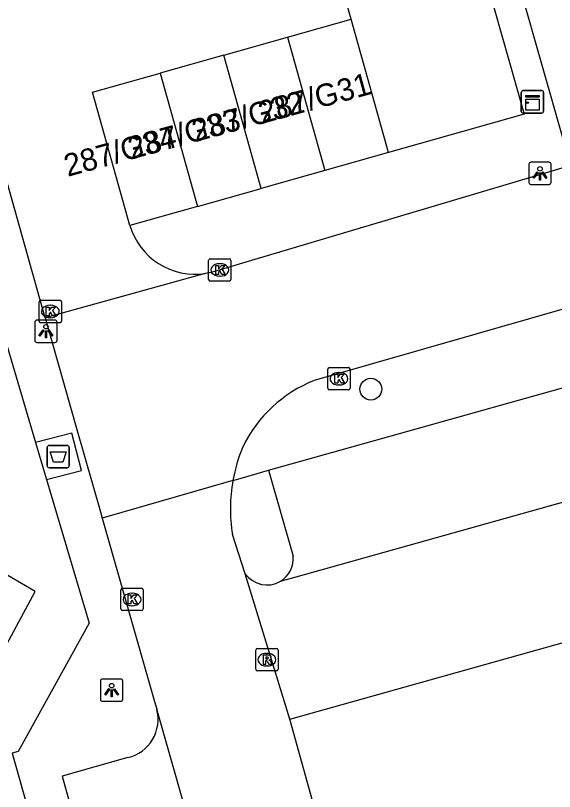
# Model space of a CAD drawing. Extents: x 159689 to 160786, y 387323 to 388339.
# Drawn here: x 159796.06 to 159820.18, y 387937.49 to 387972.19 of the extents above; entities that cross this region are included whole.
import ezdxf

# ---------------------------------------------------------------- set-up
doc = ezdxf.new("R2010")
doc.units = 0
for name, color, linetype in [('IMGEO_Afval_apart_plaats', 7, 'Continuous'), ('IMGEO_Boom', 7, 'Continuous'), ('IMGEO_Kast', 7, 'Continuous'), ('IMGEO_Kolk', 7, 'Continuous'), ('IMGEO_Lichtpunt', 7, 'Continuous'), ('IMGEO_Pand', 7, 'Continuous'), ('IMGEO_Pand_nummerreeks', 7, 'Continuous'), ('IMGEO_Rijbaan_lokaal_open', 7, 'Continuous'), ('IMGEO_Rioolput', 7, 'Continuous'), ('IMGEO_Voetpad_gesloten', 7, 'Continuous'), ('IMGEO_Voetpad_open', 7, 'Continuous')]:
    doc.layers.add(name, color=color, linetype=linetype)

msp = doc.modelspace()

# ---------------------------------------------------------------- linework, layer by layer
at = {"layer": 'IMGEO_Afval_apart_plaats'}
for p, q in [((159797.479, 387952.066), (159797.479, 387952.866)), ((159797.479, 387952.866), (159797.479, 387952.066)), ((159797.579, 387952.966), (159798.369, 387952.966)), ((159798.369, 387952.966), (159797.579, 387952.966)), ((159798.469, 387952.866), (159798.469, 387952.066)), ((159798.469, 387952.066), (159798.469, 387952.866)), ((159798.369, 387951.966), (159797.579, 387951.966)), ((159797.579, 387951.966), (159798.369, 387951.966))]:
    msp.add_line(p, q, dxfattribs=at)
msp.add_lwpolyline([(159797.622, 387952.68), (159798.326, 387952.68), (159798.177, 387952.21), (159797.771, 387952.21), (159797.622, 387952.68)], dxfattribs=at)
for centre, start, end in [((159797.579, 387952.866), 90, 180), ((159797.579, 387952.866), 90, 180), ((159798.369, 387952.866), 0, 90), ((159798.369, 387952.866), 360, 90), ((159797.579, 387952.066), 180, 270), ((159797.579, 387952.066), 180, 270), ((159798.369, 387952.066), 270, 0), ((159798.369, 387952.066), 270, 0)]:
    msp.add_arc(centre, 0.1, start, end, dxfattribs=at)
at = {"layer": 'IMGEO_Boom'}
msp.add_circle((159811.962, 387955.482), 0.489, dxfattribs=at)
at = {"layer": 'IMGEO_Kast'}
for p, q in [((159818.695, 387967.903), (159818.695, 387968.744)), ((159818.695, 387968.744), (159818.695, 387967.903)), ((159818.77, 387968.828), (159819.611, 387968.828)), ((159819.611, 387968.828), (159818.77, 387968.828)), ((159819.695, 387968.753), (159819.695, 387967.912)), ((159819.695, 387967.912), (159819.695, 387968.753)), ((159819.62, 387967.828), (159818.779, 387967.828)), ((159818.779, 387967.828), (159819.62, 387967.828))]:
    msp.add_line(p, q, dxfattribs=at)
for points in [[(159818.89, 387968.618), (159819.49, 387968.618), (159819.49, 387968.533), (159818.89, 387968.533), (159818.89, 387968.618)], [(159818.89, 387968.443), (159819.49, 387968.443), (159819.49, 387967.954), (159818.89, 387967.954), (159818.89, 387968.443)]]:
    msp.add_lwpolyline(points, dxfattribs=at)
msp.add_circle((159818.974, 387968.292), 0.0377, dxfattribs=at)
for centre, start, end in [((159818.773, 387968.75), 92.4484, 184.2845), ((159818.773, 387968.75), 92.4484, 184.2845), ((159819.617, 387968.75), 2.4484, 94.2845), ((159819.617, 387968.75), 2.4484, 94.2845), ((159818.773, 387967.906), 182.4484, 274.2845), ((159818.773, 387967.906), 182.4484, 274.2845), ((159819.617, 387967.906), 272.4484, 4.2845), ((159819.617, 387967.906), 272.4484, 4.2845)]:
    msp.add_arc(centre, 0.0779, start, end, dxfattribs=at)
at = {"layer": 'IMGEO_Kolk'}
for p, q in [((159804.704, 387960.386), (159804.704, 387961.238)), ((159804.779, 387961.312), (159805.631, 387961.312)), ((159805.705, 387961.238), (159805.705, 387960.386)), ((159805.192, 387961.092), (159805.217, 387961.092)), ((159805.215, 387960.532), (159805.19, 387960.532)), ((159805.631, 387960.312), (159804.779, 387960.312)), ((159797.122, 387958.527), (159797.122, 387959.379)), ((159797.197, 387959.453), (159798.049, 387959.453)), ((159798.123, 387959.379), (159798.123, 387958.527)), ((159797.61, 387959.233), (159797.635, 387959.233)), ((159797.633, 387958.673), (159797.608, 387958.673)), ((159798.049, 387958.453), (159797.197, 387958.453)), ((159810.036, 387955.521), (159810.036, 387956.373)), ((159810.111, 387956.447), (159810.963, 387956.447)), ((159811.037, 387956.373), (159811.037, 387955.521)), ((159810.524, 387956.227), (159810.549, 387956.227)), ((159810.547, 387955.667), (159810.522, 387955.667)), ((159810.963, 387955.447), (159810.111, 387955.447)), ((159800.856, 387946.577), (159801.708, 387946.577)), ((159800.781, 387945.651), (159800.781, 387946.503)), ((159801.269, 387946.357), (159801.294, 387946.357)), ((159801.782, 387946.503), (159801.782, 387945.651)), ((159801.708, 387945.577), (159800.856, 387945.577)), ((159801.292, 387945.797), (159801.267, 387945.797))]:
    msp.add_line(p, q, dxfattribs=at)
for points in [[(159804.704, 387960.386), (159804.704, 387961.238)], [(159804.779, 387961.312), (159805.631, 387961.312)], [(159805.705, 387961.238), (159805.705, 387960.386)], [(159805.025, 387961.012), (159805.148, 387961.012), (159805.148, 387960.861), (159805.278, 387961.012), (159805.442, 387961.012), (159805.296, 387960.861), (159805.449, 387960.612), (159805.297, 387960.612), (159805.212, 387960.776), (159805.148, 387960.709), (159805.148, 387960.612), (159805.025, 387960.612), (159805.025, 387961.012)], [(159805.631, 387960.312), (159804.779, 387960.312)], [(159797.122, 387958.527), (159797.122, 387959.379)], [(159797.197, 387959.453), (159798.049, 387959.453)], [(159798.123, 387959.379), (159798.123, 387958.527)], [(159797.443, 387959.153), (159797.566, 387959.153), (159797.566, 387959.002), (159797.696, 387959.153), (159797.86, 387959.153), (159797.714, 387959.002), (159797.867, 387958.753), (159797.715, 387958.753), (159797.63, 387958.917), (159797.566, 387958.85), (159797.566, 387958.753), (159797.443, 387958.753), (159797.443, 387959.153)], [(159798.049, 387958.453), (159797.197, 387958.453)], [(159810.036, 387955.521), (159810.036, 387956.373)], [(159810.111, 387956.447), (159810.963, 387956.447)], [(159811.037, 387956.373), (159811.037, 387955.521)], [(159810.357, 387956.147), (159810.48, 387956.147), (159810.48, 387955.996), (159810.61, 387956.147), (159810.774, 387956.147), (159810.628, 387955.996), (159810.781, 387955.747), (159810.629, 387955.747), (159810.544, 387955.911), (159810.48, 387955.844), (159810.48, 387955.747), (159810.357, 387955.747), (159810.357, 387956.147)], [(159810.963, 387955.447), (159810.111, 387955.447)], [(159800.856, 387946.577), (159801.708, 387946.577)], [(159800.781, 387945.651), (159800.781, 387946.503)], [(159801.102, 387946.277), (159801.225, 387946.277), (159801.225, 387946.126), (159801.355, 387946.277), (159801.519, 387946.277), (159801.373, 387946.126), (159801.526, 387945.877), (159801.374, 387945.877), (159801.289, 387946.041), (159801.225, 387945.974), (159801.225, 387945.877), (159801.102, 387945.877), (159801.102, 387946.277)], [(159801.782, 387946.503), (159801.782, 387945.651)], [(159801.708, 387945.577), (159800.856, 387945.577)]]:
    msp.add_lwpolyline(points, dxfattribs=at)
for centre, start, end in [((159804.781, 387961.236), 91.552, 178.448), ((159804.781, 387961.236), 91.552, 178.448), ((159805.629, 387961.236), 1.552, 88.448), ((159805.629, 387961.236), 1.552, 88.448), ((159804.781, 387960.388), 181.552, 268.448), ((159804.781, 387960.388), 181.552, 268.448), ((159805.629, 387960.388), 271.552, 358.448), ((159805.629, 387960.388), 271.552, 358.448), ((159797.199, 387959.377), 91.552, 178.448), ((159797.199, 387959.377), 91.552, 178.448), ((159798.047, 387959.377), 1.552, 88.448), ((159798.047, 387959.377), 1.552, 88.448), ((159797.199, 387958.529), 181.552, 268.448), ((159797.199, 387958.529), 181.552, 268.448), ((159798.047, 387958.529), 271.552, 358.448), ((159798.047, 387958.529), 271.552, 358.448), ((159810.113, 387956.371), 91.552, 178.448), ((159810.113, 387956.371), 91.552, 178.448), ((159810.961, 387956.371), 1.552, 88.448), ((159810.961, 387956.371), 1.552, 88.448), ((159810.113, 387955.523), 181.552, 268.448), ((159810.113, 387955.523), 181.552, 268.448), ((159810.961, 387955.523), 271.552, 358.448), ((159810.961, 387955.523), 271.552, 358.448), ((159800.858, 387946.501), 91.552, 178.448), ((159800.858, 387946.501), 91.552, 178.448), ((159801.706, 387946.501), 1.552, 88.448), ((159801.706, 387946.501), 1.552, 88.448), ((159800.858, 387945.653), 181.552, 268.448), ((159800.858, 387945.653), 181.552, 268.448), ((159801.706, 387945.653), 271.552, 358.448), ((159801.706, 387945.653), 271.552, 358.448)]:
    msp.add_arc(centre, 0.0765, start, end, dxfattribs=at)
for centre, major_axis, ratio, start_param, end_param in [((159805.191, 387960.812), (-0.387, 0.002), 0.722429, 4.712389, 7.853982), ((159805.216, 387960.812), (-0.39, 0.002), 0.717154, 1.570796, 4.712389), ((159797.609, 387958.953), (-0.387, 0.002), 0.722429, 4.712389, 7.853982), ((159797.634, 387958.953), (-0.39, 0.002), 0.717154, 1.570796, 4.712389), ((159810.523, 387955.947), (-0.387, 0.002), 0.722429, 4.712389, 7.853982), ((159810.548, 387955.947), (-0.39, 0.002), 0.717154, 1.570796, 4.712389), ((159801.268, 387946.077), (-0.387, 0.002), 0.722429, 4.712389, 7.853982), ((159801.293, 387946.077), (-0.39, 0.002), 0.717154, 1.570796, 4.712389)]:
    msp.add_ellipse(centre, major_axis=major_axis, ratio=ratio, start_param=start_param, end_param=end_param, dxfattribs=at)
at = {"layer": 'IMGEO_Lichtpunt'}
for p, q in [((159819.935, 387965.629), (159819.127, 387965.629)), ((159819.935, 387965.629), (159819.127, 387965.629)), ((159819.033, 387965.534), (159819.033, 387964.727)), ((159819.033, 387965.534), (159819.033, 387964.727)), ((159820.029, 387964.727), (159820.029, 387965.534)), ((159820.029, 387964.727), (159820.029, 387965.534)), ((159819.127, 387964.633), (159819.935, 387964.633)), ((159819.127, 387964.633), (159819.935, 387964.633)), ((159796.926, 387958.474), (159796.926, 387957.667)), ((159796.926, 387958.474), (159796.926, 387957.667)), ((159797.828, 387958.569), (159797.02, 387958.569)), ((159797.828, 387958.569), (159797.02, 387958.569)), ((159797.922, 387957.667), (159797.922, 387958.474)), ((159797.922, 387957.667), (159797.922, 387958.474)), ((159797.02, 387957.573), (159797.828, 387957.573)), ((159797.02, 387957.573), (159797.828, 387957.573)), ((159799.867, 387942.424), (159799.867, 387941.617)), ((159799.867, 387942.424), (159799.867, 387941.617)), ((159800.769, 387942.519), (159799.961, 387942.519)), ((159800.769, 387942.519), (159799.961, 387942.519)), ((159800.863, 387941.617), (159800.863, 387942.424)), ((159800.863, 387941.617), (159800.863, 387942.424)), ((159799.961, 387941.523), (159800.769, 387941.523)), ((159799.961, 387941.523), (159800.769, 387941.523))]:
    msp.add_line(p, q, dxfattribs=at)
for points in [[(159819.407, 387965.198), (159819.446, 387965.17), (159819.258, 387964.908), (159819.22, 387964.935), (159819.407, 387965.198)], [(159819.509, 387965.15), (159819.556, 387965.15), (159819.556, 387964.828), (159819.509, 387964.828), (159819.509, 387965.15)], [(159819.619, 387965.17), (159819.657, 387965.197), (159819.844, 387964.935), (159819.805, 387964.907), (159819.619, 387965.17)], [(159797.3, 387958.138), (159797.339, 387958.11), (159797.151, 387957.848), (159797.113, 387957.875), (159797.3, 387958.138)], [(159797.402, 387958.09), (159797.449, 387958.09), (159797.449, 387957.768), (159797.402, 387957.768), (159797.402, 387958.09)], [(159797.512, 387958.11), (159797.55, 387958.137), (159797.737, 387957.875), (159797.698, 387957.847), (159797.512, 387958.11)], [(159800.241, 387942.088), (159800.28, 387942.06), (159800.092, 387941.798), (159800.054, 387941.825), (159800.241, 387942.088)], [(159800.343, 387942.04), (159800.39, 387942.04), (159800.39, 387941.718), (159800.343, 387941.718), (159800.343, 387942.04)], [(159800.453, 387942.06), (159800.491, 387942.087), (159800.678, 387941.825), (159800.639, 387941.797), (159800.453, 387942.06)]]:
    msp.add_lwpolyline(points, dxfattribs=at)
for centre in [(159819.532, 387965.332), (159797.425, 387958.272), (159800.366, 387942.222)]:
    msp.add_circle(centre, 0.0994, dxfattribs=at)
for centre, start, end in [((159819.127, 387965.534), 90, 180), ((159819.127, 387965.534), 90, 180), ((159819.935, 387965.534), 0, 90), ((159819.935, 387965.534), 0, 90), ((159819.127, 387964.727), 180, 270), ((159819.127, 387964.727), 180, 270), ((159819.935, 387964.727), 270, 0), ((159819.935, 387964.727), 270, 360), ((159797.02, 387958.474), 90, 180), ((159797.02, 387958.474), 90, 180), ((159797.828, 387958.474), 0, 90), ((159797.828, 387958.474), 0, 90), ((159797.02, 387957.667), 180, 270), ((159797.02, 387957.667), 180, 270), ((159797.828, 387957.667), 270, 0), ((159797.828, 387957.667), 270, 360), ((159799.961, 387942.424), 90, 180), ((159799.961, 387942.424), 90, 180), ((159800.769, 387942.424), 0, 90), ((159800.769, 387942.424), 0, 90), ((159799.961, 387941.617), 180, 270), ((159799.961, 387941.617), 180, 270), ((159800.769, 387941.617), 270, 0), ((159800.769, 387941.617), 270, 360)]:
    msp.add_arc(centre, 0.0946, start, end, dxfattribs=at)
at = {"layer": 'IMGEO_Pand'}
for points in [[(159816.341, 387976.561), (159817.139, 387973.727), (159818.817, 387967.77), (159812.759, 387966.064)], [(159811.081, 387972.02), (159810.283, 387974.854)], [(159808.231, 387971.217), (159811.081, 387972.02)], [(159812.759, 387966.064), (159811.081, 387972.02)], [(159805.381, 387970.414), (159808.231, 387971.217)], [(159808.231, 387971.217), (159809.909, 387965.261)], [(159805.381, 387970.414), (159802.531, 387969.611)], [(159807.059, 387964.458), (159805.381, 387970.414)], [(159801.187, 387962.804), (159799.509, 387968.76), (159802.531, 387969.611)], [(159802.531, 387969.611), (159804.209, 387963.655)], [(159812.759, 387966.064), (159809.909, 387965.261)], [(159809.909, 387965.261), (159807.059, 387964.458)], [(159804.209, 387963.655), (159807.059, 387964.458)], [(159804.209, 387963.655), (159801.187, 387962.804)], [(159817.654, 387873.188), (159814.236, 387875.206), (159812.839, 387874.816), (159811.729, 387878.794), (159794.957, 387938.93), (159793.845, 387942.918), (159795.243, 387943.308), (159796.937, 387946.428), (159793.873, 387948.22), (159792.476, 387947.83), (159790.044, 387956.547)]]:
    msp.add_lwpolyline(points, dxfattribs=at)
at = {"layer": 'IMGEO_Rijbaan_lokaal_open'}
for points in [[(159797.394, 387958.677), (159795.106, 387966.751)], [(159824.35, 387966.504), (159823.817, 387966.352), (159804.968, 387960.744), (159804.858, 387960.713), (159804.82, 387960.704), (159804.552, 387960.652)], [(159801.187, 387962.804), (159801.275, 387962.547), (159801.387, 387962.298), (159801.519, 387962.06), (159801.673, 387961.836), (159801.846, 387961.625), (159802.037, 387961.432), (159802.245, 387961.255), (159802.467, 387961.099), (159802.703, 387960.962), (159802.95, 387960.848), (159803.206, 387960.756), (159803.469, 387960.687), (159803.738, 387960.642), (159804.009, 387960.621), (159804.282, 387960.624), (159804.552, 387960.652)], [(159804.552, 387960.652), (159797.394, 387958.677)], [(159826.008, 387960.718), (159821.548, 387959.345), (159809.432, 387955.868)], [(159797.394, 387958.677), (159798.81, 387953.681), (159799.862, 387949.988), (159799.939, 387949.715)], [(159807.916, 387946.888), (159808.628, 387947.088), (159828.468, 387952.653)], [(159805.793, 387951.397), (159799.939, 387949.715)], [(159799.939, 387949.715), (159802.277, 387941.509), (159802.383, 387941.169)], [(159806.346, 387947.229), (159805.768, 387948.986)], [(159808.337, 387940.72), (159806.346, 387947.229)], [(159808.337, 387940.72), (159830.103, 387946.826)], [(159818.713, 387883.386), (159807.156, 387924.411), (159802.383, 387941.169)], [(159811.326, 387930.006), (159808.337, 387940.72)]]:
    msp.add_lwpolyline(points, dxfattribs=at)
for centre, radius, start, end in [((159811.653, 387950.267), 6.025, 111.6351, 154.1542), ((159812.846, 387950.146), 7.163, 157.4411, 169.9415), ((159812.928, 387950.117), 7.249, 169.8327, 188.9791), ((159807.315, 387947.905), 1.182, 214.917, 300.5747)]:
    msp.add_arc(centre, radius, start, end, dxfattribs=at)
at = {"layer": 'IMGEO_Rioolput'}
for p, q in [((159806.811, 387942.958), (159806.811, 387943.81)), ((159806.886, 387943.884), (159807.738, 387943.884)), ((159807.812, 387943.81), (159807.812, 387942.958)), ((159807.299, 387943.664), (159807.324, 387943.664)), ((159807.322, 387943.104), (159807.297, 387943.104)), ((159807.738, 387942.884), (159806.886, 387942.884))]:
    msp.add_line(p, q, dxfattribs=at)
for points in [[(159806.811, 387942.958), (159806.811, 387943.81)], [(159806.886, 387943.884), (159807.738, 387943.884)], [(159807.812, 387943.81), (159807.812, 387942.958)], [(159807.4, 387943.582), (159807.148, 387943.584), (159807.148, 387943.184)], [(159807.326, 387943.503), (159807.272, 387943.503), (159807.272, 387943.422)], [(159807.272, 387943.422), (159807.324, 387943.422)], [(159807.148, 387943.184), (159807.272, 387943.184), (159807.272, 387943.346), (159807.283, 387943.346)], [(159807.33, 387943.317), (159807.401, 387943.184), (159807.541, 387943.184), (159807.476, 387943.31)], [(159807.738, 387942.884), (159806.886, 387942.884)]]:
    msp.add_lwpolyline(points, dxfattribs=at)
for centre, radius, start, end in [((159806.888, 387943.808), 0.0765, 91.552, 178.448), ((159806.888, 387943.808), 0.0765, 91.552, 178.448), ((159807.736, 387943.808), 0.0765, 1.552, 88.448), ((159807.736, 387943.808), 0.0765, 1.552, 88.448), ((159807.308, 387943.611), 0.19, 274.7715, 282.9687), ((159807.332, 387943.407), 0.0964, 77.0061, 93.1865), ((159807.346, 387943.464), 0.0378, 276.6634, 79.6772), ((159807.399, 387943.472), 0.109, 350.3612, 89.416), ((159807.397, 387943.472), 0.112, 277.5842, 350.9817), ((159807.282, 387943.293), 0.0533, 26.0293, 88.6989), ((159807.381, 387943.257), 0.108, 29.5134, 73.7905), ((159806.888, 387942.96), 0.0765, 181.552, 268.448), ((159806.888, 387942.96), 0.0765, 181.552, 268.448), ((159807.736, 387942.96), 0.0765, 271.552, 358.448), ((159807.736, 387942.96), 0.0765, 271.552, 358.448)]:
    msp.add_arc(centre, radius, start, end, dxfattribs=at)
for centre, major_axis, ratio, start_param, end_param in [((159807.298, 387943.384), (-0.387, 0.002), 0.722429, 4.712389, 7.853982), ((159807.323, 387943.384), (-0.39, 0.002), 0.717154, 1.570796, 4.712389)]:
    msp.add_ellipse(centre, major_axis=major_axis, ratio=ratio, start_param=start_param, end_param=end_param, dxfattribs=at)
at = {"layer": 'IMGEO_Voetpad_gesloten'}
for points in [[(159797.453, 387951.445), (159799.011, 387951.842), (159798.586, 387953.509), (159796.965, 387953.096)], [(159796.965, 387953.096), (159797.453, 387951.445)]]:
    msp.add_lwpolyline(points, dxfattribs=at)
at = {"layer": 'IMGEO_Voetpad_open'}
for points in [[(159827.327, 387968.664), (159820.56, 387966.714), (159818.739, 387973.12), (159826.587, 387975.306)], [(159790.044, 387956.547), (159795.499, 387958.055), (159796.965, 387953.096)], [(159807.384, 387951.855), (159807.645, 387951.93), (159827.139, 387957.391)], [(159805.793, 387951.397), (159806.109, 387951.488), (159807.384, 387951.855)], [(159807.384, 387951.855), (159808.488, 387948.019)], [(159797.453, 387951.445), (159799.354, 387945.014), (159796.181, 387939.271), (159795.919, 387939.198), (159812.869, 387879.112), (159822.604, 387873.593), (159837.725, 387877.749)], [(159801.092, 387939.006), (159798.147, 387938.168), (159813.659, 387882.338), (159817.555, 387883.408)]]:
    msp.add_lwpolyline(points, dxfattribs=at)
for centre, radius, start, end in [((159807.316, 387947.902), 1.178, 300.6362, 5.7081), ((159800.692, 387940.712), 1.752, 283.2062, 15.1316)]:
    msp.add_arc(centre, radius, start, end, dxfattribs=at)

# ---------------------------------------------------------------- texts
at = {"layer": 'IMGEO_Pand_nummerreeks'}
for s, p in [('287/G31', (159807.096, 387967.344)), ('287/G32', (159804.119, 387966.532)), ('287/G33', (159801.26, 387965.753)), ('287/G34', (159798.396, 387964.971))]:
    msp.add_text(s, height=1, rotation=15.2551, dxfattribs=at).set_placement(p)

doc.saveas('drawing.dxf')
